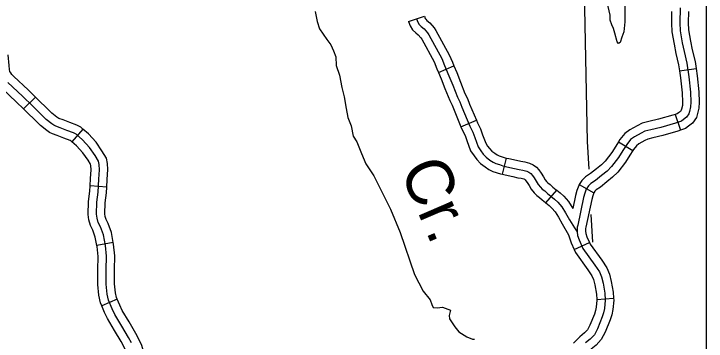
# Model space of a CAD drawing. Extents: x -5566 to 1759129, y -3726 to 731467.
# Drawn here: x -4493.76 to -4446.6, y 331.44 to 353.7 of the extents above; entities that cross this region are included whole.
import ezdxf

# ---------------------------------------------------------------- set-up
doc = ezdxf.new("R2010")
doc.units = 0
doc.layers.add('Default', color=7, linetype='Continuous')
doc.layers.add('R_No Plot', color=7, linetype='Continuous')

msp = doc.modelspace()

# ---------------------------------------------------------------- linework, layer by layer
at = {"layer": 'Default'}
for p, q in [((-4466.87, 353.175), (-4465.794, 353.548)), ((-4464.84, 349.722), (-4463.791, 350.168)), ((-4448.416, 349.816), (-4447.289, 349.985)), ((-4492.3, 348.041), (-4493.103, 347.232)), ((-4448.72, 346.856), (-4448.351, 345.779)), ((-4463.305, 346.022), (-4462.255, 346.465)), ((-4489.054, 345.855), (-4489.814, 345.006)), ((-4452.57, 345.005), (-4451.606, 344.397)), ((-4460.486, 342.789), (-4460.209, 343.894)), ((-4487.434, 341.92), (-4488.571, 341.991)), ((-4455.245, 342.091), (-4454.253, 341.526)), ((-4457.521, 340.842), (-4456.77, 341.698)), ((-4486.988, 338.152), (-4488.108, 337.939)), ((-4455.592, 337.674), (-4454.552, 338.138)), ((-4486.733, 334.292), (-4487.781, 333.845)), ((-4454.047, 334.274), (-4452.912, 334.365))]:
    msp.add_line(p, q, dxfattribs=at)
for points in [[(-4455.01, 358.933), (-4454.913, 355.227), (-4454.699, 345.015), (-4454.604, 343.131)], [(-4452.013, 355.208), (-4452.162, 354.954), (-4452.162, 354.61), (-4452.147, 354.131), (-4452.147, 353.713), (-4452.132, 353.159), (-4452.222, 352.486), (-4452.342, 352.113), (-4452.461, 351.754), (-4452.581, 351.694), (-4452.656, 351.799), (-4452.835, 352.382), (-4452.91, 352.696), (-4453.029, 352.95), (-4453.134, 353.264), (-4453.134, 353.623), (-4453.268, 354.191), (-4453.358, 354.714), (-4453.388, 354.924), (-4453.388, 355.133), (-4453.612, 355.357), (-4453.851, 355.507)], [(-4473.236, 353.852), (-4473.098, 353.186), (-4472.935, 352.681), (-4472.453, 351.959), (-4472.167, 351.604), (-4471.992, 351.183), (-4471.826, 350.785), (-4471.812, 350.184), (-4471.583, 349.529), (-4471.431, 348.681), (-4471.271, 348.047), (-4471.121, 347.267), (-4471.022, 346.645), (-4470.782, 346.075), (-4470.643, 345.386), (-4470.393, 344.992)], [(-4448.383, 354.108), (-4448.391, 353.087), (-4448.372, 352.546), (-4448.228, 351.736), (-4448.107, 351.131), (-4447.919, 350.345), (-4447.779, 349.413), (-4447.673, 348.365), (-4447.641, 347.703), (-4447.659, 347.367), (-4447.739, 347.067), (-4447.78, 346.897), (-4447.948, 346.662), (-4448.142, 346.518), (-4448.293, 346.4), (-4448.697, 346.262), (-4449.7, 345.979), (-4450.365, 345.819), (-4450.77, 345.718), (-4451.039, 345.583), (-4451.494, 345.33), (-4451.746, 345.146), (-4452.015, 344.816), (-4452.281, 344.395), (-4452.568, 343.935), (-4453.047, 343.31), (-4453.351, 343.006), (-4453.725, 342.71), (-4454.142, 342.371), (-4454.455, 342.166), (-4454.625, 341.997), (-4454.768, 341.779), (-4454.864, 341.501), (-4454.951, 341.205), (-4455.353, 339.323), (-4455.395, 339.179), (-4455.399, 338.883), (-4455.358, 338.629), (-4455.264, 338.335), (-4454.999, 337.742), (-4454.184, 336.613), (-4453.878, 336.144), (-4453.737, 335.814), (-4453.63, 335.383), (-4453.51, 334.701), (-4453.472, 334.23), (-4453.522, 333.665), (-4453.585, 333.37), (-4453.686, 333.081), (-4454.006, 332.277), (-4454.219, 331.875), (-4454.496, 331.58), (-4454.822, 331.31)], [(-4448.954, 353.863), (-4448.961, 353.079), (-4448.939, 352.486), (-4448.788, 351.631), (-4448.664, 351.009), (-4448.479, 350.236), (-4448.416, 349.816)], [(-4447.815, 353.854), (-4447.822, 353.095), (-4447.804, 352.607), (-4447.668, 351.841), (-4447.551, 351.253), (-4447.36, 350.454), (-4447.289, 349.985)], [(-4466.332, 353.362), (-4466.254, 353.135), (-4466.158, 352.979), (-4466.01, 352.831), (-4465.819, 352.683), (-4465.593, 352.413), (-4465.497, 352.275), (-4464.619, 350.675), (-4464.419, 350.188), (-4464.123, 349.492), (-4463.871, 348.839), (-4463.551, 348.042), (-4463.377, 347.711), (-4463.247, 347.347), (-4462.699, 346.051), (-4462.499, 345.651), (-4462.368, 345.286), (-4462.134, 344.651), (-4461.951, 344.372), (-4461.786, 344.164), (-4461.586, 343.946), (-4461.334, 343.755), (-4461.116, 343.611), (-4460.929, 343.516), (-4460.69, 343.442), (-4460.451, 343.368), (-4460.173, 343.298), (-4459.655, 343.185), (-4459.334, 343.111), (-4459.081, 343.076), (-4458.829, 343.007), (-4458.686, 342.937), (-4458.555, 342.841), (-4458.442, 342.715), (-4458.316, 342.55), (-4458.173, 342.319), (-4458.047, 342.098), (-4457.899, 341.911), (-4457.768, 341.78), (-4457.603, 341.65), (-4457.408, 341.48), (-4457.181, 341.302), (-4456.934, 341.084), (-4456.708, 340.888), (-4456.438, 340.584), (-4456.177, 340.171), (-4455.912, 339.692), (-4455.581, 339.136), (-4455.399, 338.883)], [(-4465.794, 353.548), (-4465.735, 353.38), (-4465.707, 353.334), (-4465.633, 353.259), (-4465.422, 353.096), (-4465.139, 352.759), (-4465.012, 352.575), (-4464.104, 350.921), (-4463.893, 350.407), (-4463.791, 350.168)], [(-4466.87, 353.175), (-4466.772, 352.891), (-4466.609, 352.624), (-4466.387, 352.403), (-4466.216, 352.27), (-4466.046, 352.068), (-4465.982, 351.975), (-4465.133, 350.429), (-4464.944, 349.968), (-4464.84, 349.722)], [(-4492.3, 348.041), (-4492.785, 348.522), (-4493.772, 349.444), (-4493.898, 349.573), (-4493.978, 349.691), (-4494.027, 349.79), (-4494.059, 349.922), (-4494.094, 350.186), (-4494.14, 350.909), (-4494.14, 350.91)], [(-4493.103, 347.232), (-4493.575, 347.702), (-4494.569, 348.629), (-4494.784, 348.85), (-4494.963, 349.114), (-4495.104, 349.396), (-4495.181, 349.713), (-4495.228, 350.075), (-4495.277, 350.837), (-4495.277, 350.839)], [(-4463.791, 350.168), (-4463.595, 349.706), (-4463.341, 349.048), (-4463.033, 348.281), (-4462.854, 347.941), (-4462.716, 347.554), (-4462.255, 346.465)], [(-4447.289, 349.985), (-4447.214, 349.484), (-4447.105, 348.407), (-4447.071, 347.701), (-4447.094, 347.277), (-4447.187, 346.927), (-4447.251, 346.657), (-4447.537, 346.257), (-4447.798, 346.065), (-4448.019, 345.892), (-4448.351, 345.779)], [(-4464.84, 349.722), (-4464.651, 349.278), (-4464.401, 348.631), (-4464.069, 347.803), (-4463.9, 347.482), (-4463.777, 347.14), (-4463.305, 346.022)], [(-4448.416, 349.816), (-4448.344, 349.341), (-4448.241, 348.322), (-4448.211, 347.704), (-4448.225, 347.456), (-4448.292, 347.206), (-4448.308, 347.138), (-4448.359, 347.066), (-4448.486, 346.972), (-4448.568, 346.908), (-4448.72, 346.856)], [(-4485.756, 331.319), (-4485.957, 331.681), (-4486.405, 332.455), (-4486.875, 333.253), (-4487.07, 333.632), (-4487.323, 334.223), (-4487.412, 334.641), (-4487.472, 335.308), (-4487.484, 336.284), (-4487.449, 337.225), (-4487.53, 337.949), (-4487.667, 338.672), (-4487.862, 339.209), (-4488.012, 339.51), (-4488.098, 339.801), (-4488.126, 340.082), (-4488.103, 340.89), (-4488.026, 341.581), (-4487.971, 342.463), (-4487.929, 343.101), (-4487.957, 343.443), (-4487.994, 343.68), (-4488.235, 344.059), (-4488.611, 344.61), (-4489.088, 345.12), (-4489.53, 345.516), (-4489.7, 345.61), (-4490.156, 345.774), (-4490.605, 345.951), (-4490.911, 346.067), (-4491.048, 346.129), (-4491.178, 346.215), (-4491.565, 346.524), (-4491.898, 346.856), (-4492.482, 347.418), (-4493.18, 348.112), (-4494.171, 349.036)], [(-4489.054, 345.855), (-4489.198, 345.983), (-4489.464, 346.131), (-4489.956, 346.307), (-4490.4, 346.482), (-4490.692, 346.593), (-4490.77, 346.628), (-4490.842, 346.676), (-4491.185, 346.949), (-4491.499, 347.263), (-4492.083, 347.825), (-4492.3, 348.041)], [(-4489.814, 345.006), (-4489.862, 345.049), (-4489.936, 345.09), (-4490.357, 345.241), (-4490.81, 345.419), (-4491.131, 345.541), (-4491.326, 345.63), (-4491.513, 345.755), (-4491.944, 346.098), (-4492.297, 346.449), (-4492.88, 347.011), (-4493.103, 347.232)], [(-4448.72, 346.856), (-4448.867, 346.806), (-4449.844, 346.53), (-4450.501, 346.372), (-4450.968, 346.255), (-4451.305, 346.087), (-4451.801, 345.811), (-4452.141, 345.563), (-4452.478, 345.149), (-4452.57, 345.005)], [(-4462.255, 346.465), (-4462.181, 346.29), (-4461.974, 345.875), (-4461.833, 345.48), (-4461.622, 344.909), (-4461.489, 344.706), (-4461.352, 344.534), (-4461.201, 344.369), (-4461.004, 344.22), (-4460.829, 344.104), (-4460.714, 344.045), (-4460.298, 343.916), (-4460.209, 343.894)], [(-4487.434, 341.92), (-4487.403, 342.426), (-4487.358, 343.105), (-4487.391, 343.511), (-4487.45, 343.886), (-4487.76, 344.372), (-4488.165, 344.967), (-4488.689, 345.528), (-4489.054, 345.855)], [(-4463.305, 346.022), (-4463.216, 345.813), (-4463.024, 345.427), (-4462.904, 345.091), (-4462.645, 344.392), (-4462.413, 344.039), (-4462.219, 343.794), (-4461.971, 343.523), (-4461.663, 343.29), (-4461.404, 343.119), (-4461.145, 342.986), (-4460.604, 342.819), (-4460.486, 342.789)], [(-4448.351, 345.779), (-4448.527, 345.718), (-4449.556, 345.428), (-4450.23, 345.266), (-4450.571, 345.181), (-4450.773, 345.079), (-4451.186, 344.85), (-4451.351, 344.729), (-4451.552, 344.483), (-4451.606, 344.397)], [(-4488.571, 341.991), (-4488.54, 342.499), (-4488.5, 343.097), (-4488.523, 343.375), (-4488.538, 343.474), (-4488.711, 343.745), (-4489.057, 344.253), (-4489.487, 344.713), (-4489.814, 345.006)], [(-4470.393, 344.992), (-4470.084, 344.19), (-4469.777, 343.497), (-4469.239, 342.686), (-4468.747, 341.682), (-4468.101, 340.417), (-4467.444, 338.833), (-4466.474, 335.979), (-4465.886, 334.842), (-4465.401, 334.242), (-4465.298, 333.918), (-4465.192, 333.716), (-4464.926, 333.695), (-4464.563, 333.739), (-4464.024, 333.537), (-4464.118, 333.183), (-4464.087, 332.956), (-4463.718, 332.413), (-4463.44, 332.072), (-4462.895, 331.719), (-4462.518, 331.58), (-4462.389, 331.569)], [(-4452.57, 345.005), (-4452.763, 344.698), (-4453.036, 344.26), (-4453.476, 343.687), (-4453.73, 343.432), (-4454.081, 343.155), (-4454.479, 342.832), (-4454.816, 342.611), (-4455.069, 342.359), (-4455.245, 342.091)], [(-4451.606, 344.397), (-4451.798, 344.093), (-4452.099, 343.61), (-4452.618, 342.934), (-4452.972, 342.58), (-4453.369, 342.266), (-4453.806, 341.91), (-4454.094, 341.722), (-4454.181, 341.635), (-4454.253, 341.526)], [(-4460.209, 343.894), (-4460.043, 343.853), (-4459.531, 343.741), (-4459.231, 343.672), (-4458.966, 343.635), (-4458.628, 343.542), (-4458.391, 343.427), (-4458.171, 343.266), (-4458.003, 343.079), (-4457.847, 342.874), (-4457.683, 342.611), (-4457.573, 342.417), (-4457.473, 342.29), (-4457.389, 342.206), (-4457.24, 342.089), (-4457.044, 341.919), (-4456.817, 341.74), (-4456.77, 341.698)], [(-4460.486, 342.789), (-4460.303, 342.743), (-4459.78, 342.629), (-4459.437, 342.55), (-4459.197, 342.517), (-4459.031, 342.471), (-4458.981, 342.447), (-4458.94, 342.417), (-4458.882, 342.352), (-4458.785, 342.226), (-4458.662, 342.028), (-4458.52, 341.778), (-4458.325, 341.531), (-4458.148, 341.354), (-4457.966, 341.211), (-4457.771, 341.041), (-4457.546, 340.864), (-4457.521, 340.842)], [(-4488.108, 337.939), (-4488.218, 338.52), (-4488.387, 338.985), (-4488.544, 339.301), (-4488.659, 339.69), (-4488.697, 340.061), (-4488.672, 340.93), (-4488.594, 341.631), (-4488.571, 341.991)], [(-4486.988, 338.152), (-4487.116, 338.823), (-4487.338, 339.434), (-4487.479, 339.719), (-4487.536, 339.911), (-4487.556, 340.103), (-4487.535, 340.85), (-4487.459, 341.532), (-4487.434, 341.92)], [(-4455.245, 342.091), (-4455.285, 342.03), (-4455.407, 341.674), (-4455.504, 341.345), (-4455.691, 340.468)], [(-4456.77, 341.698), (-4456.559, 341.514), (-4456.306, 341.294), (-4455.981, 340.927), (-4455.691, 340.468)], [(-4454.253, 341.526), (-4454.321, 341.328), (-4454.399, 341.065), (-4454.8, 339.184), (-4454.826, 339.094), (-4454.829, 338.925), (-4454.802, 338.762), (-4454.731, 338.539), (-4454.552, 338.138)], [(-4457.521, 340.842), (-4457.308, 340.655), (-4457.109, 340.483), (-4456.895, 340.241), (-4456.667, 339.881), (-4456.406, 339.409), (-4455.971, 338.677)], [(-4454.449, 340.053), (-4454.354, 338.163)], [(-4455.971, 338.677), (-4455.797, 338.131), (-4455.592, 337.674)], [(-4486.733, 334.292), (-4486.777, 334.396), (-4486.848, 334.726), (-4486.903, 335.337), (-4486.914, 336.277), (-4486.878, 337.246), (-4486.966, 338.033), (-4486.988, 338.152)], [(-4487.781, 333.845), (-4487.868, 334.05), (-4487.976, 334.556), (-4488.041, 335.279), (-4488.053, 336.291), (-4488.02, 337.204), (-4488.093, 337.864), (-4488.108, 337.939)], [(-4455.592, 337.674), (-4455.495, 337.457), (-4454.654, 336.291), (-4454.383, 335.875), (-4454.279, 335.632), (-4454.188, 335.265), (-4454.076, 334.629), (-4454.047, 334.274)], [(-4454.552, 338.138), (-4454.503, 338.028), (-4453.714, 336.936), (-4453.374, 336.414), (-4453.195, 335.996), (-4453.073, 335.502), (-4452.944, 334.774), (-4452.912, 334.365)], [(-4484.919, 330.719), (-4484.92, 330.721), (-4484.925, 330.751), (-4485.046, 331.129), (-4485.247, 331.574), (-4485.462, 331.962), (-4485.913, 332.742), (-4486.376, 333.528), (-4486.555, 333.874), (-4486.733, 334.292)], [(-4454.047, 334.274), (-4454.044, 334.233), (-4454.087, 333.75), (-4454.135, 333.523), (-4454.22, 333.28), (-4454.524, 332.517), (-4454.687, 332.209), (-4454.887, 331.996), (-4455.203, 331.734), (-4455.647, 331.302)], [(-4452.912, 334.365), (-4452.901, 334.228), (-4452.958, 333.58), (-4453.036, 333.216), (-4453.152, 332.882), (-4453.488, 332.037), (-4453.752, 331.541), (-4454.105, 331.164), (-4454.441, 330.886), (-4454.853, 330.486)], [(-4485.974, 330.288), (-4486.02, 330.401), (-4486.033, 330.476), (-4486.111, 330.72), (-4486.266, 331.063), (-4486.453, 331.401), (-4486.897, 332.168), (-4487.374, 332.978), (-4487.586, 333.389), (-4487.781, 333.845)]]:
    msp.add_lwpolyline(points, dxfattribs=at)
at = {"layer": 'R_No Plot'}
msp.add_lwpolyline([(-5018.988, 168.239), (-5018.988, 511.979), (-4446.603, 511.979), (-4446.603, 160.504), (-4913.433, 160.504)], dxfattribs=at)

# ---------------------------------------------------------------- texts
at = {"layer": 'Default'}
msp.add_text('Cr.', height=3.2048, rotation=293.2445, dxfattribs=at).set_placement((-4467.512, 343.109))

doc.saveas('drawing.dxf')
